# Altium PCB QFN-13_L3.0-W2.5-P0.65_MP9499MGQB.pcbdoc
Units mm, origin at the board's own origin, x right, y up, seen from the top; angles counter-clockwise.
Board outline 16.03 x 16.3 mm, 2 copper layers (Top Layer, Bottom Layer), stack 0 mm thick; 1 components, 0 nets, 13 pads, 0 vias.
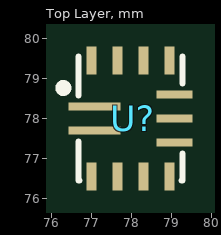
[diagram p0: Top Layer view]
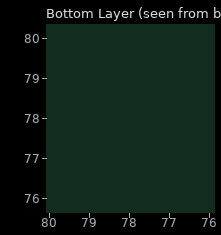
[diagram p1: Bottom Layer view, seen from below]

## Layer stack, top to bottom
Top Layer: signal copper (thickness not stored)
Bottom Layer: signal copper (thickness not stored)

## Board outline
85.878,69.85 69.85,69.85 69.85,86.15 85.878,86.15

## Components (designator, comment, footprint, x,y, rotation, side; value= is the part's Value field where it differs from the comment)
U? "" QFN-13_L3.0-W2.5-P0.65_MP9499MGQB 78.041,78 r0 top

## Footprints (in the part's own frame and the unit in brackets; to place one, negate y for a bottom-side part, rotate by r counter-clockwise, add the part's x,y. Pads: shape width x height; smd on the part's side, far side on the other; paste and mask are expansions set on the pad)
QFN-13_L3.0-W2.5-P0.65_MP9499MGQB [mm]
  rect 1.3x0.2 smd paste+0 mask+0.05: 1(-0.963,0.3) 2(-0.963,-0.3)
  rect 0.25x0.7 smd paste+0 mask+0.05: 3(-1.037,-1.45) 4(-0.387,-1.45) 5(0.263,-1.45) 6(0.912,-1.45) 10(0.912,1.45) 11(0.263,1.45) 12(-0.387,1.45) 13(-1.037,1.45)
  rect 0.9x0.2 smd paste+0 mask+0.05: 7(1.037,-0.6) 8(1.037,0) 9(1.037,0.6)
  silkscreen extent -1.84,-1.55 1.24,1.55

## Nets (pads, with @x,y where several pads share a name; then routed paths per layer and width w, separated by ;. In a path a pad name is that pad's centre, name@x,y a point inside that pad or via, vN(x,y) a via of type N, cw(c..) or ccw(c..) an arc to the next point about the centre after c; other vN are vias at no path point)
pads on no net: U?.1 U?.2 U?.3 U?.4 U?.5 U?.6 U?.7 U?.8 U?.9 U?.10 U?.11 U?.12 U?.13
